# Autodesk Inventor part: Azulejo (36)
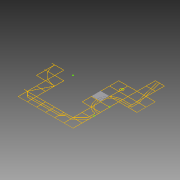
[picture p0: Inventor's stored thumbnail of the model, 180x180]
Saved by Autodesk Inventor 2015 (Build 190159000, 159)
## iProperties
Created: 2015-04
Part Number: Azulejo (36)
Material: Genérico
Document SubType Name: Modeling
Designer: Felipe
Density: 1 g/cm^3
Appearance: Padrão
Author: Felipe
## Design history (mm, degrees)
sketch "Sketch1"
  geometry: L1 (-1510, -7490)-(-1510, -6010); L2 (-3010, -1490)-(-3010, -10); L3 (-2990, 10)-(-1510, 10); L4 (-1510, -10)-(-2990, -10); L5 (-1510, -1490)-(-1510, -10); L6 (-1490, -10)-(-1490, -1490); L7 (-1490, -1490)-(-10, -1490); L8 (-10, -1510)-(-1490, -1510); L9 (-10, -2990)-(-10, -1510); L10 (-10, -5990)-(-10, -4510); L11 (-1490, -7490)-(-10, -7490); L12 (4490, -6010)-(3010, -6010); L13 (10, -1510)-(10, -2990); L14 (10, -3010)-(10, -4490); L15 (10, -4510)-(10, -5990); L16 (10, -5990)-(1490, -5990); L17 (1490, -6010)-(10, -6010); L18 (10, -7490)-(1490, -7490); L19 (1510, -5990)-(2990, -5990); L20 (2990, -6010)-(1510, -6010); L21 (1510, -7490)-(2990, -7490); L22 (4490, 1510)-(4490, 2990); L23 (4490, 10)-(4490, 1490); L24 (4490, -1490)-(4490, -10); L25 (4490, -2990)-(4490, -1510); L26 (3010, -5990)-(4490, -5990); L27 (3010, -7490)-(4490, -7490); L28 (4510, 3010)-(5990, 3010); L29 (5990, 2990)-(4510, 2990); L30 (4510, 2990)-(4510, 1510); L31 (4510, 1510)-(5990, 1510); L32 (5990, 1510)-(5990, 1740.185); L33 (5990, 1760.2)-(5990, 2259.8); L34 (5990, 2279.815)-(5990, 2990); L35 (5990, 1490)-(4510, 1490); L36 (4510, 1490)-(4510, 10); L37 (4510, 10)-(5990, 10); L38 (5990, 10)-(5990, 1490); L39 (5975.983, -10)-(4510, -10); L40 (4510, -10)-(4510, -1490); L41 (5990, -1510)-(5782.897, -1510); L42 (5782.897, -1510)-(5688.66, -1510); L43 (5668.66, -1510)-(5482.895, -1510); L44 (5482.895, -1510)-(5388.656, -1510); L45 (5368.656, -1510)-(4510, -1510); L46 (4510, -1510)-(4510, -2990); L47 (4510, -2990)-(5975.983, -2990); L48 (5990, -2975.728)-(5990, -2837.377); L49 (5990, -2837.377)-(5990, -2536.247); L50 (5990, -2500.476)-(5990, -2317.632); L51 (5990, -2317.632)-(5990, -1510); L52 (5990, -3010)-(4510, -3010); L53 (5990, -4490)-(5990, -3010); L54 (4510, -5990)-(5990, -5990); L55 (5990, -5990)-(5990, -4510); L56 (4510, -7490)-(5990, -7490); L57 (5990, -7490)-(5990, -6310); L58 (5990, -6290)-(5990, -6010); L59 (7490, 4510)-(7490, 5990); L60 (6010, 3010)-(7490, 3010); L61 (7490, 3010)-(7490, 4490); L62 (7490, 2990)-(6010, 2990); L63 (6010, 2990)-(6010, 2279.815); L64 (6010, 2259.8)-(6010, 1760.2)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; A1 r 250 centre (6000, 2010) between (5990, 2259.8) and (5990, 1760.2); A2 r 250 centre (6000, 2010) between (6010, 1760.2) and (6010, 2259.8); A3 r 270 centre (6000, 2010) between (5990, 2279.815) and (5990, 1740.185); A4 r 270 centre (6000, 2010) between (6010, 1740.185) and (6010, 2279.815); A5 r 3010.017 centre (0, 0) between (-1490, -2615.358) and (-346.554, -2990); A6 r 2990.017 centre (0, 0) between (-1490, -2592.316) and (-10, -2990); A7 r 3010.017 centre (0, 0) between (-2603.863, -1510) and (-1510, -2603.863); A8 r 2990.017 centre (0, 0) between (-2580.717, -1510) and (-1510, -2580.717); A9 r 3010.017 centre (0, 0) between (-2990, -346.554) and (-2615.358, -1490); A10 r 2990.017 centre (0, 0) between (-2990, -10) and (-2592.316, -1490); A11 r 2131.367 centre (7500, -1500) between (7490, 631.344) and (6010, 24.017); A12 r 2131.367 centre (7500, -1500) between (5975.983, -10) and (5368.656, -1490); A13 r 2131.367 centre (7500, -1500) between (5368.656, -1510) and (5975.983, -2990); A14 r 2131.367 centre (7500, -1500) between (6010, -3024.017) and (7190, -3608.703); A15 r 1831.367 centre (7500, -1500) between (7490.321, 331.342) and (6463.753, 10); A16 r 1831.367 centre (7500, -1500) between (6435.196, -10) and (6010, -435.196); A17 r 1831.367 centre (7500, -1500) between (5990, -463.753) and (5668.66, -1490); A18 r 1831.367 centre (7500, -1500) between (5668.66, -1510) and (5990, -2536.247); A19 r 1831.367 centre (7500, -1500) between (6010, -2564.804) and (6435.196, -2990); A20 r 1831.367 centre (7500, -1500) between (6463.753, -3010) and (7490, -3331.34); A21 r 2111.367 centre (7500, -1500) between (7490.047, 611.344) and (6024.272, 10); A22 r 2111.367 centre (7500, -1500) between (5990, -24.272) and (5388.656, -1490); A23 r 2111.367 centre (7500, -1500) between (5388.656, -1510) and (5990, -2975.728); A24 r 2111.367 centre (7500, -1500) between (6024.272, -3010) and (7210, -3591.357); A25 r 1811.367 centre (7500, -1500) between (7490.374, 311.342) and (6499.524, 10); A26 r 1811.367 centre (7500, -1500) between (6469.975, -10) and (6010, -469.975); A27 r 1811.367 centre (7500, -1500) between (5990, -499.524) and (5688.66, -1490); A28 r 1811.367 centre (7500, -1500) between (5688.66, -1510) and (5990, -2500.476); A29 r 1811.367 centre (7500, -1500) between (6010, -2530.025) and (6469.975, -2990); A30 r 1811.367 centre (7500, -1500) between (6499.524, -3010) and (7490, -3311.34); A31 r 449.871 centre (7499.449, -4060.672) between (7510, -4510.419) and (7521.546, -4510); 10 further points
  constraints: 698 end point, 64 point on circle, 31 centre point, 11 point on line, 1 other
extrude "Extrusion1" new body sketch "Sketch1" distance "d0" = 60; taper "d1" = 0 deg
extrude "Extrusion2" new body sketch "Sketch1" distance "d2" = 60; taper "d3" = 0 deg
extrude "Extrusion3" new body sketch "Sketch1" distance "d4" = 60; taper "d5" = 0 deg
body "Solid1"
body "Solid2"
body "Solid3"
